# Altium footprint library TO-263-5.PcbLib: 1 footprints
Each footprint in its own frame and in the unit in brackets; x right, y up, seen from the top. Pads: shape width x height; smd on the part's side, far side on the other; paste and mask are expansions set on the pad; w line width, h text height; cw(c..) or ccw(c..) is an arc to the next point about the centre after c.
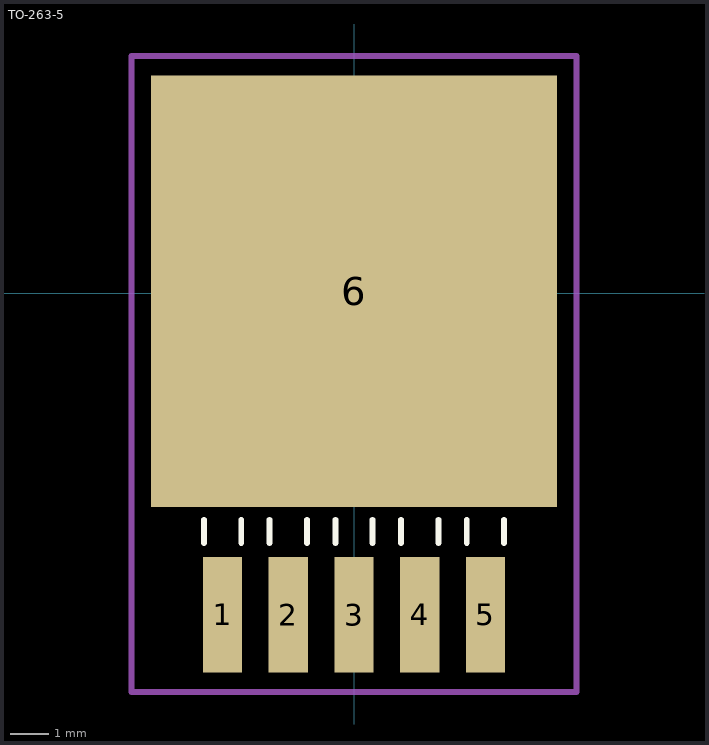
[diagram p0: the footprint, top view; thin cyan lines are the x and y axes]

## TO-263-5 [mil]
pads (6):
  rect 40x118 smd: 1(-134,-328) 2(-67,-328) 3(0,-328) 4(67,-328) 5(134,-328)
  rect 414x440 smd: 6(0,2)
Top Overlay:
  lines w6: -153,-255 -153,-231.1 ; -115,-255 -115,-231.1 ; -86,-255 -86,-231.1 ; -48,-255 -48,-231.1 ; -19,-255 -19,-231.1 ; 19,-255 19,-231.1 ; 48,-255 48,-231.1 ; 86,-255 86,-231.1 ; 115,-255 115,-231.1 ; 153,-255 153,-231.1
Mechanical 15:
  lines w6: -227,-407 -227,-238 -227,242 227,242 227,-238 227,-407 -227,-407
3D body "TS5B.step": height 189.09, standoff -2.01, extent -205,-277.52 205,200.12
